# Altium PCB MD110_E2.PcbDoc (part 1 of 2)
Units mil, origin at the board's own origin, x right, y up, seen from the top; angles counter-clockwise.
Board outline 2320.49 x 1909 mil, 4 copper layers (Top Layer, Signal Layer 1, Signal Layer 2, Bottom Layer), stack 61.2 mil thick; 89 components, 32 nets, 187 pads, 40 vias.
Unrouted connection lines stored in the file: 7.
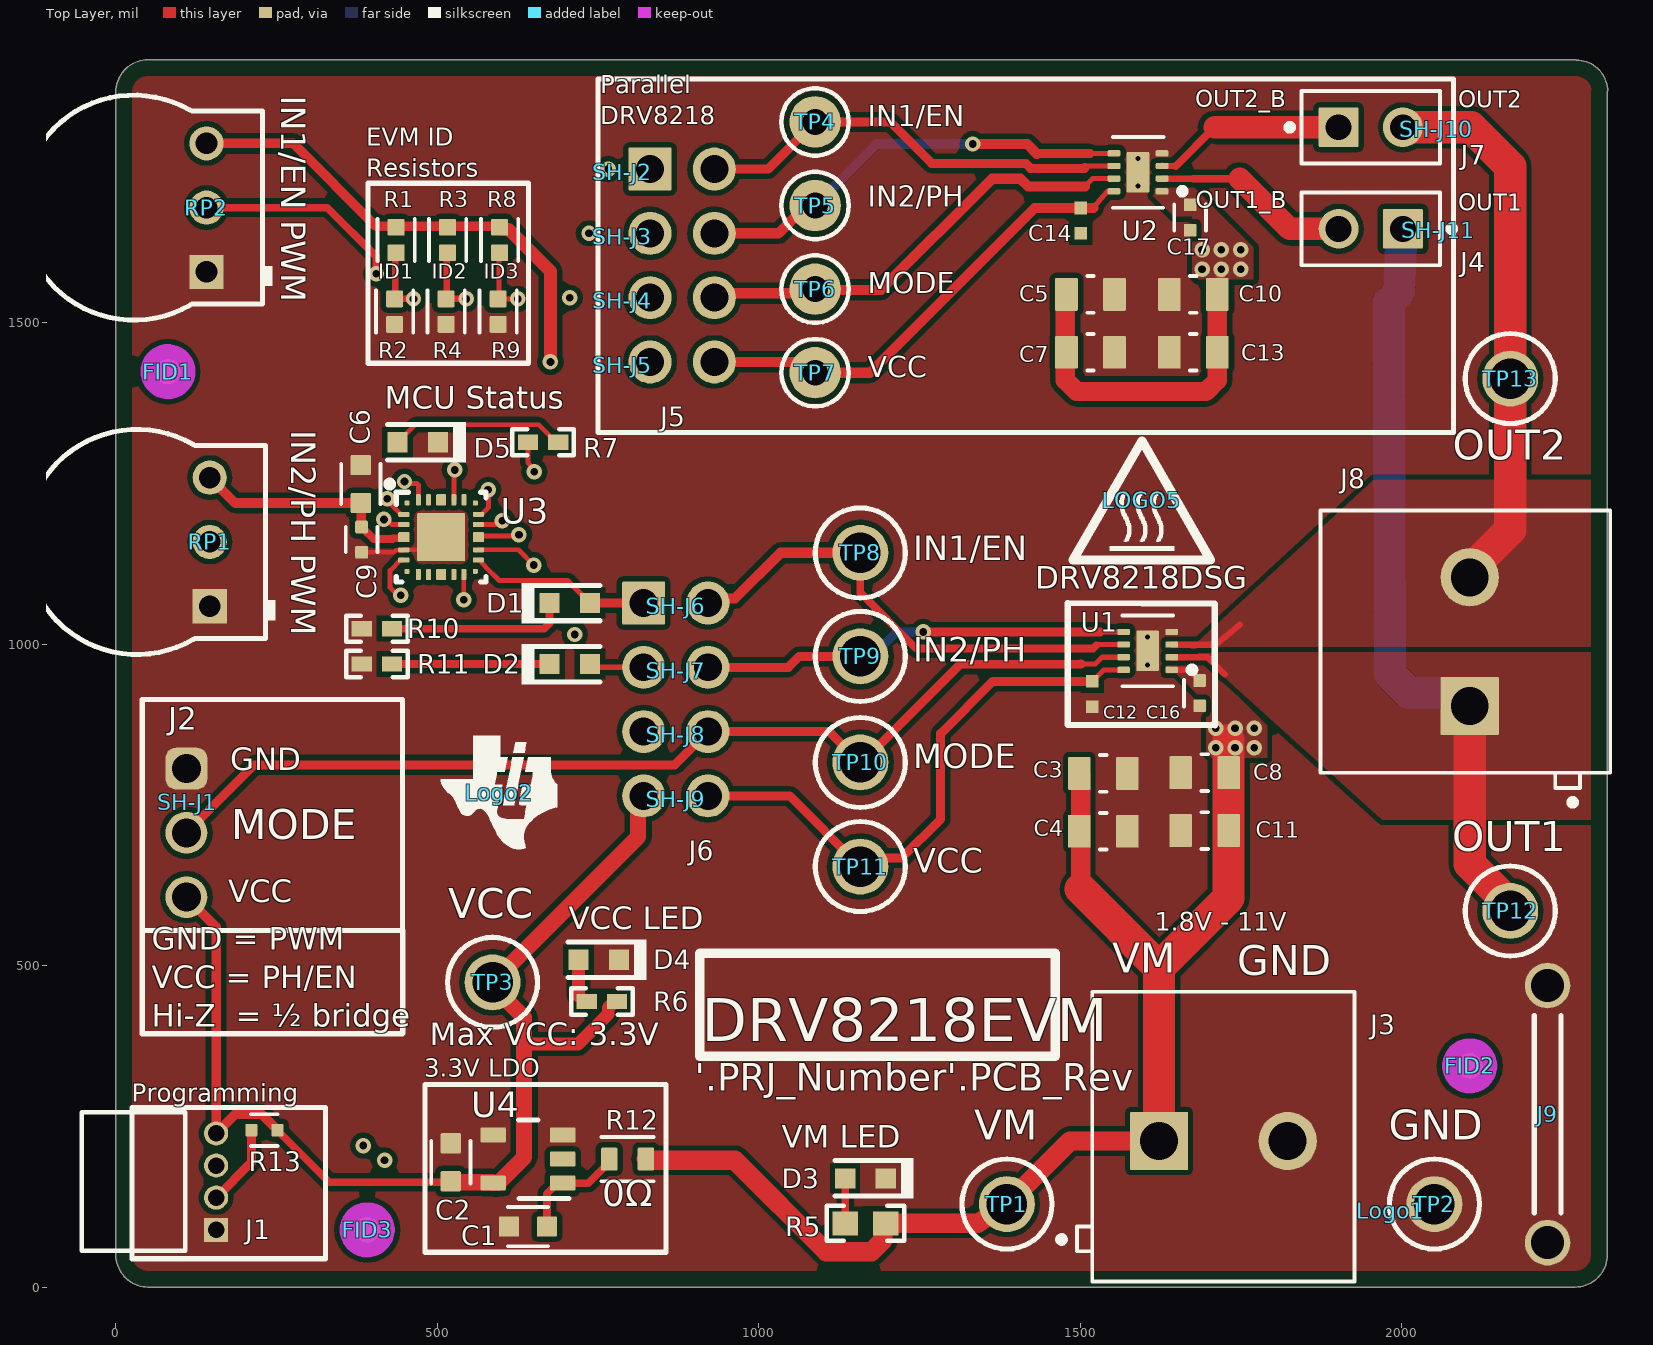
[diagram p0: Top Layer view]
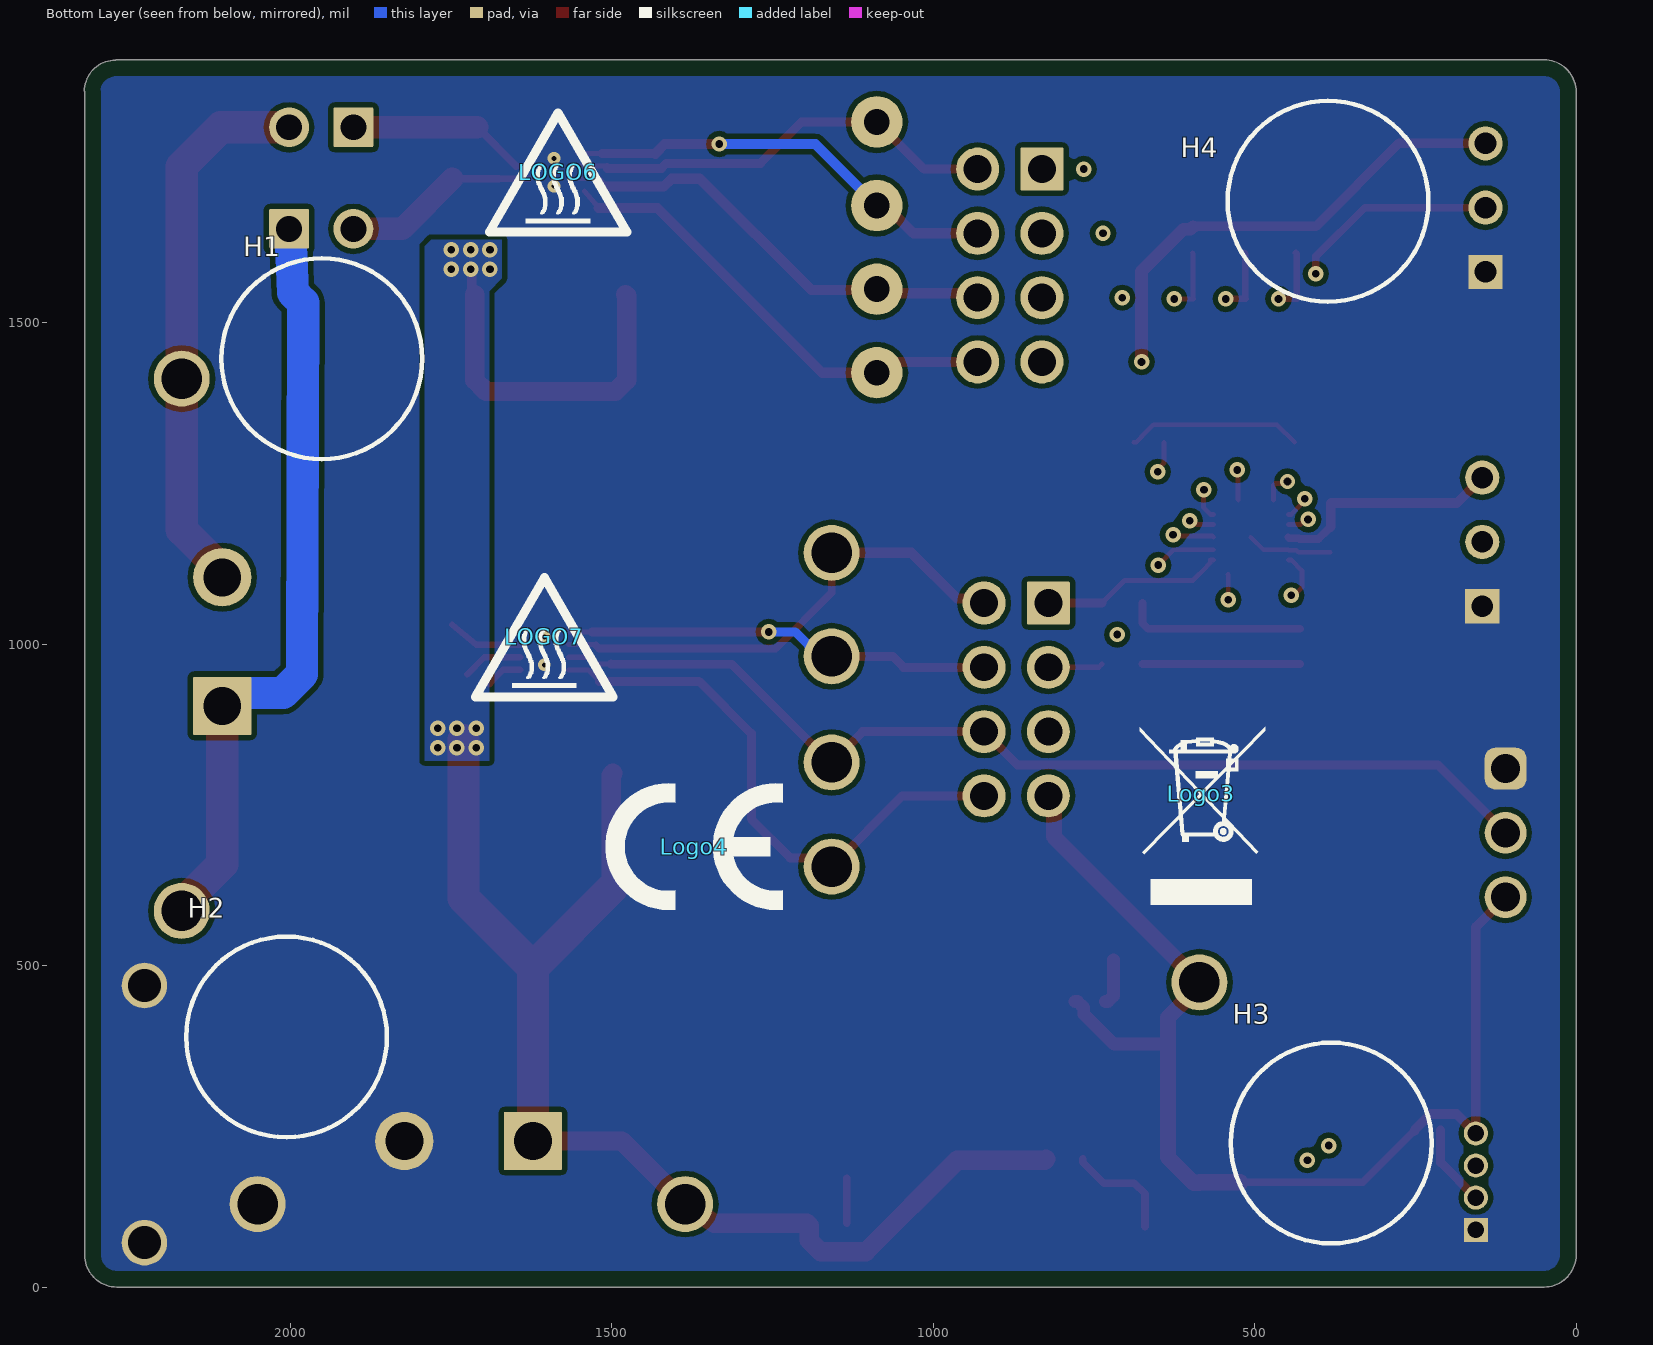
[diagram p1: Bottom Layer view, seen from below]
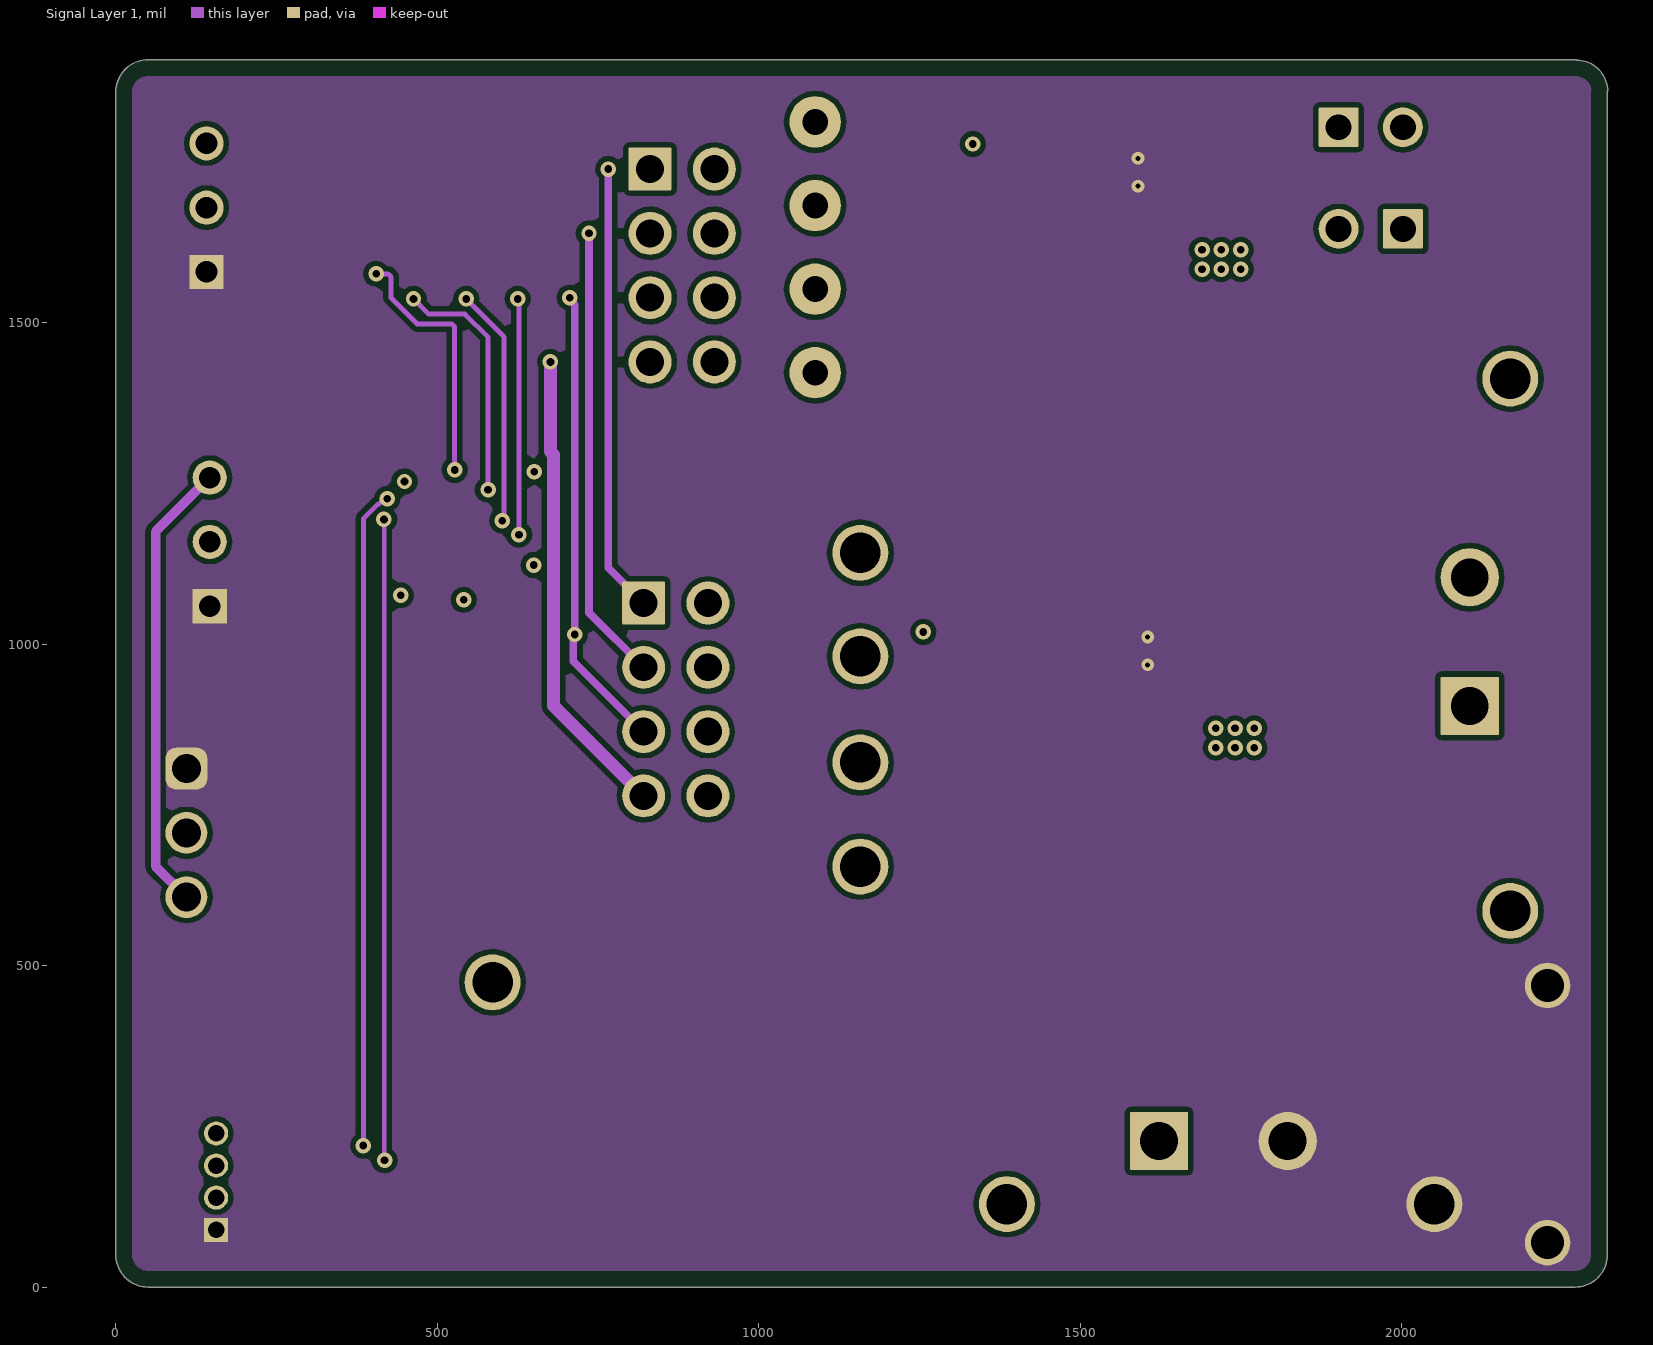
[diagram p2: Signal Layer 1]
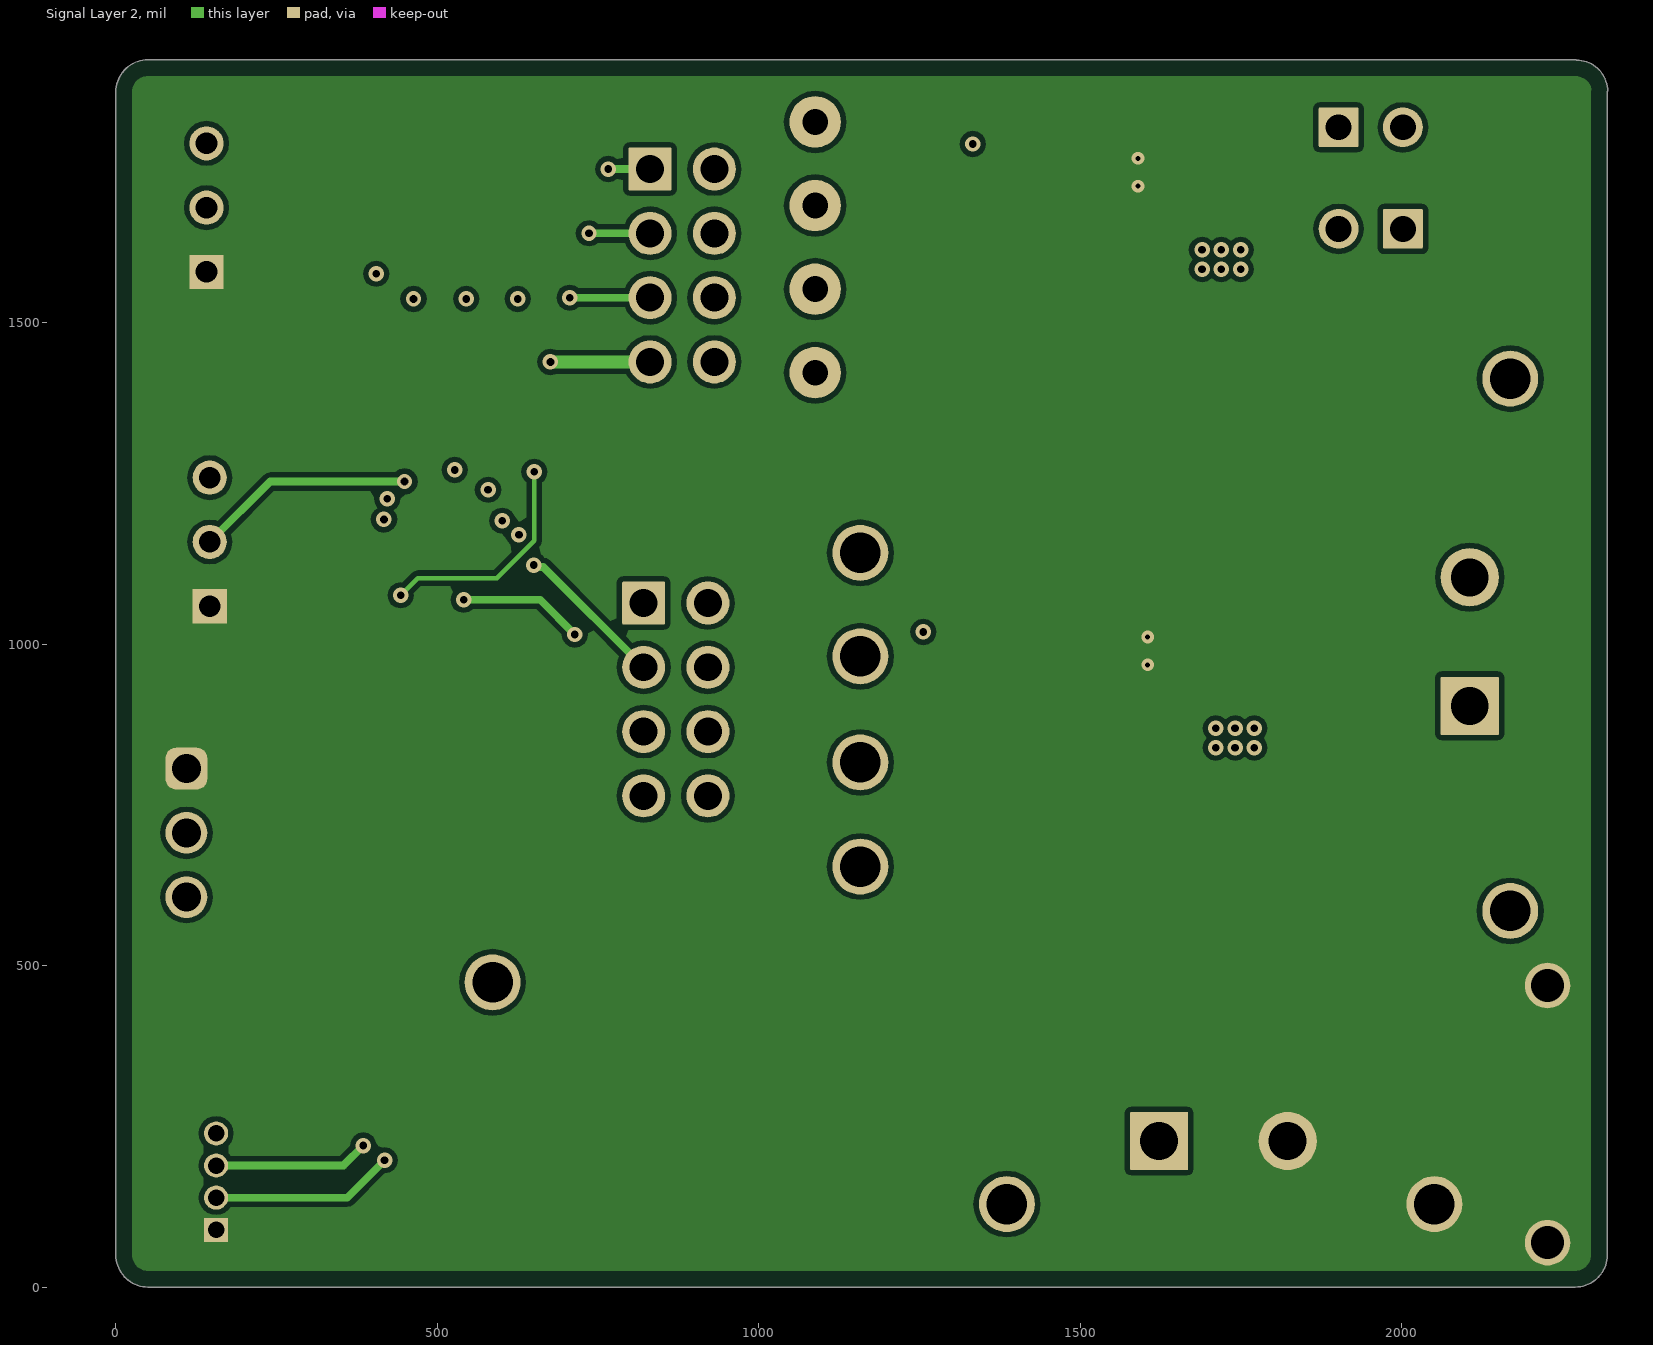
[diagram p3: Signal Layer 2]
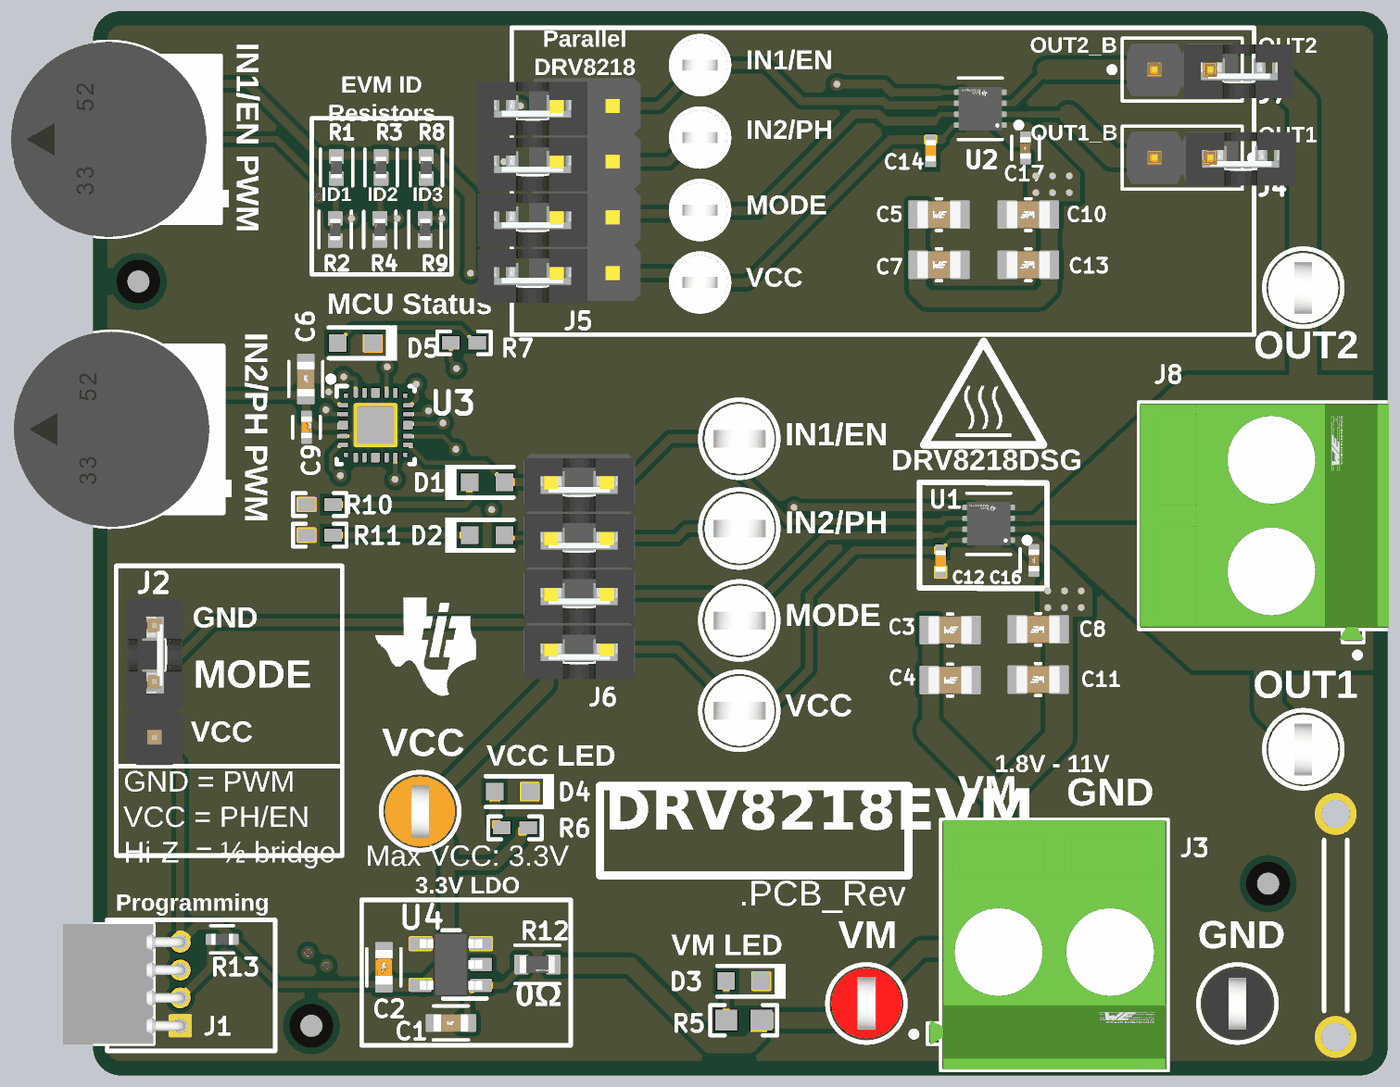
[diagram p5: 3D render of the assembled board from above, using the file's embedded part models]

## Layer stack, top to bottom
Top Solder: solder mask 0.4, Solder Resist, Dk 3.5
Top Layer: signal copper 2.8
Dielectric 1: prepreg 11.4, FR4 370, Dk 4.2
Signal Layer 1: signal copper 1.4
Dielectric 2: core 30, FR4 370, Dk 4.2
Signal Layer 2: signal copper 1.4
Dielectric 3: prepreg 11.4, FR4 370, Dk 4.2
Bottom Layer: signal copper 2.8
Bottom Solder: solder mask 0.4, Solder Resist, Dk 3.5

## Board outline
50,0 cw(c50,50) 0,50 0,1859 cw(c50,1859) 50,1909 2272,1909 2272,1908.49 cw(c2272,1860) 2320.49,1860 2320,1860 2320,50 cw(c2270,50) 2270,0

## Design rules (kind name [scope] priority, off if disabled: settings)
AcuteAngle [All] p1: minimum=4.50000000000000E+0001 checktracksonly=FALSE
AssemblyTestPointUsage [All] p1: valid=2
BoardOutlineClearance BoardOutlineClearance_MountingHoles [OnCopper and InComponentClass('Mounting Holes')] p1: gap=25 ignorepadtopadclearanceinfootprint=FALSE
BoardOutlineClearance BoardOutlineClearance_Poly [OnCopper and IsPoly] p2: gap=25 ignorepadtopadclearanceinfootprint=FALSE
BoardOutlineClearance [OnCopper and Not InComponentClass('Logo') and not InComponentClass('FiducialMark') and not InRegion(1000,500,4000,800) and not InPoly] p3: gap=10 ignorepadtopadclearanceinfootprint=FALSE
Clearance Clearance_OUTx [InNet('OUT1')] p1: gap=8 ignorepadtopadclearanceinfootprint=TRUE
Clearance Clearance_Keepouts [((IsTrack Or IsArc) And Not InPoly) And IsFree and IsKeepOut vs ((IsTrack Or IsArc) And Not InPoly) And IsFree and IsKeepOut] p2: gap=0 ignorepadtopadclearanceinfootprint=FALSE
Clearance Clearance_FiducialMark [IsKeepOut and InComponentClass('FiducialMark') vs IsPad and InComponentClass('FiducialMark')] p3: gap=0 ignorepadtopadclearanceinfootprint=FALSE
Clearance Clearance_Poly [InPolygon] p4: gap=8 ignorepadtopadclearanceinfootprint=TRUE
Clearance [All] p5: gap=7.87 ignorepadtopadclearanceinfootprint=TRUE
ComponentClearance ComponentClearance_Shunt2Header [InComponentClass('Header') vs InComponentClass('Shunt')] p1: gap=0 collisioncheckmode=3 verticalgap=0 showdistances=FALSE
ComponentClearance ComponentClearance_Shunt2Shunt [InComponentClass('Shunt') vs InComponentClass('Shunt')] p2: gap=0 collisioncheckmode=3 verticalgap=0 showdistances=FALSE
ComponentClearance ComponentClearance_MountingHoles_FiducialMarks [InComponentClass('Mounting Holes') vs InComponentClass('FiducialMark')] p3: gap=50 collisioncheckmode=3 verticalgap=10 showdistances=FALSE
ComponentClearance ComponentClearance_Logo [InComponentClass('Logo')] p4: gap=50 collisioncheckmode=3 verticalgap=10 showdistances=FALSE
ComponentClearance ComponentClearance_ScrewToNut [(HasFootprint('NY PMS 440 0025 PH')) vs (HasFootprint('Keystone_1902C'))] p5: gap=5 collisioncheckmode=3 verticalgap=10 showdistances=FALSE
ComponentClearance ComponentClearance_MountingHoles [InComponentClass('Mounting Holes')] p6: gap=250 collisioncheckmode=3 verticalgap=100000 showdistances=FALSE
ComponentClearance ComponentClearance_SmallPassives [HasFootprint('0201*') or HasFootprint('0402*') or HasFootprint('0508') or HasFootprint('0603*') or HasFootprint('0612') or HasFootprint('0805*') or HasFootprint('0815*') or HasFootprint('0830*') or HasFootprint('1206*') or HasFootprint('1210*') or HasFootprint('1808*') or HasFootprint('1812*') or HasFootprint('1825*') or HasFootprint('2010*') or HasFootprint('2220*') or HasFootprint('2225*') or HasFootprint('2512*') or HasFootprint('2728*') or HasFootprint('3518*') vs HasFootprint('0201*') or HasFootprint('0402*') or HasFootprint('0508') or HasFootprint('0603*') or HasFootprint('0612') or HasFootprint('0805*') or HasFootprint('0815*') or HasFootprint('0830*') or HasFootprint('1206*') or HasFootprint('1210*') or HasFootprint('1808*') or HasFootprint('1812*') or HasFootprint('1825*') or HasFootprint('2010*') or HasFootprint('2220*') or HasFootprint('2225*') or HasFootprint('2512*') or HasFootprint('2728*') or HasFootprint('3518*')] p7: gap=14.96 collisioncheckmode=3 verticalgap=10 showdistances=FALSE
ComponentClearance ComponentClearance_THtoSMT [IsThruComponent vs IsSMTComponent] p8: gap=30 collisioncheckmode=3 verticalgap=30 showdistances=FALSE
ComponentClearance ComponentClearance_THtoTH [IsThruComponent vs IsThruComponent] p9: gap=30 collisioncheckmode=3 verticalgap=30 showdistances=FALSE
ComponentClearance [All] p10: gap=30 collisioncheckmode=3 verticalgap=10 showdistances=FALSE
DiffPairsRouting [All] p1: maxlimit=100 minlimit=10 mostfreqgap=10 toplayer_minwidth=6.3 toplayer_maxwidth=15 toplayer_prefwidth=10 midlayer1_minwidth=15 midlayer1_maxwidth=15 midlayer1_prefwidth=15 midlayer2_minwidth=15 midlayer2_maxwidth=15 midlayer2_prefwidth=15 bottomlayer_minwidth=6.3 bottomlayer_maxwidth=15 bottomlayer_prefwidth=10 maxuncoupledlength=1000
FabricationTestPointUsage TestPointUsage [All] p1: valid=2 allowmultiple=FALSE
FabricationTestpoint Testpoint [All] p1: side=3 testpointundercomponent=TRUE minsize=40 maxsize=100 preferedsize=60 minholesize=0 maxholesize=40 preferedholesize=32 testpointgrid=1 allowsidetop=TRUE allowsidebottom=TRUE usegrid=TRUE gridtolerance=0.01
FanoutControl Fanout_LCC [IsLCC] p1: bgadir=Out bgaviamode=Centered fanoutstyle=Auto fanoutdirection=Alternating viagrid=1 // Fanout_LCC (Default Rule)
FanoutControl Fanout_BGA [IsBGA] p2: bgadir=Out bgaviamode=Centered fanoutstyle=Auto fanoutdirection=Alternating viagrid=1 // Fanout_BGA (Default Rule)
FanoutControl Fanout_Default [All] p4: bgadir=Out bgaviamode=Centered fanoutstyle=Auto fanoutdirection=Alternating viagrid=1 // Fanout_Default (Default Rule)
FanoutControl Fanout_Small [(CompPinCount < 5)] p5: bgadir=Out bgaviamode=Centered fanoutstyle=Auto fanoutdirection=OutThenIn viagrid=1 // Fanout_Small (Default Rule)
HoleSize [All] p1: absolutevalues=TRUE maxlimit=251 minlimit=7.87 maxpercent=80.000 minpercent=20.000
MinimumAnnularRing MinimumAnnularRing_ThermalPadVias [IsVia and InAnyComponent] p1: minimumring=5.91
MinimumAnnularRing [All] p2: minimumring=7.87
MinimumSolderMaskSliver MinimumSolderMaskSliver_Logo [InComponentClass('Logo') vs InComponentClass('Logo')] p1: minsoldermaskwidth=0.7
MinimumSolderMaskSliver [All] p2: minsoldermaskwidth=3.94
PlaneClearance [All] p1: clearance=12
PlaneConnect [All] p1: planeconnectstyle=Direct reliefexpansion=10 reliefentries=4 reliefconductorwidth=10 reliefairgap=10
PolygonConnect PolygonConnect_1 [InNetClass('Power-Net') vs IsNamedPolygon('TOP_LAYER_EZFET_USB_SHIELD_P201')] p1: connectstyle=Direct reliefconductorwidth=10 reliefentries=4 polygonreliefangle="90 Angle" airgapwidth=10
PolygonConnect [All] p2: connectstyle=Direct reliefconductorwidth=10 reliefentries=4 polygonreliefangle="90 Angle" airgapwidth=10
RoutingVias ThermalPadVias [IsVia and InAnyComponent] p1: holewidth=7.87 width=19.68 viastyle="Through Hole" minholewidth=7.87 minwidth=19.68 maxholewidth=12.99 maxwidth=23.62
RoutingVias [All] p2: holewidth=16 width=34 viastyle="Through Hole" minholewidth=7.87 minwidth=26 maxholewidth=40 maxwidth=65
SilkToBoardRegionClearance [Not ((IsComment or IsDesignator) And (Hide <> 'False')) and not InRegion(1000,500,4000,800)] p1:
SilkToSilkClearance SilkToSilkClearance_Pb-FreeLogo [(HasFootprint('Pb-Free_Overlay_Medium') OR HasFootprint('Pb-Free_Overlay_Small')) vs (HasFootprint('Pb-Free_Overlay_Medium') OR HasFootprint('Pb-Free_Overlay_Small'))] p1: silktosilkclearance=0
SilkToSilkClearance [All] p2: silktosilkclearance=3.94
SilkToSolderMaskClearance SilkToComponentPadClearance [(IsPad or IsFill or IsRegion) and InAnycomponent] p1: minsilkscreentomaskgap=5 clearancetoexposedcopper=TRUE
SilkToSolderMaskClearance "Silk to Solder Mask Opening" [All] p2: minsilkscreentomaskgap=3.94 clearancetoexposedcopper=FALSE
SolderMaskExpansion [All] p1: expansion=1.97 istentingtop=FALSE
UnRoutedNet [All] p1: checkbadconnections=TRUE
Width [All] p1: maxlimit=65 minlimit=4 preferedwidth=15 minimp=50.000000 maximp=50.000000 favimp=50.000000 checkconnectedcopper=TRUE
13 further rules are at their usual default settings.

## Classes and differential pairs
component class Shunt: SH-J1 SH-J2 SH-J3 SH-J4 SH-J5 SH-J6 SH-J7 SH-J8 SH-J9 SH-J10 SH-J11
component class MD110_E2_Schematic: C1 C2 C3 C4 C5 C6 C7 C8 C9 C10 C11 C12 C13 C14 C16 C17 D1 D2 D3 D4 D5 J1 J2 J3 J4 J5 J6 J7 J8 J9 R1 R2 R3 R4 R5 R6 R7 R8 R9 R10 R11 R12 R13 RP1 RP2 SH-J1 SH-J2 SH-J3 SH-J4 SH-J5 SH-J6 SH-J7 SH-J8 SH-J9 SH-J10 SH-J11 TP1 TP2 TP3 TP4 TP5 TP6 TP7 TP8 TP9 TP10 TP11 TP12 TP13 U1 U2 U3 U4
component class FiducialMark: FID1 FID2 FID3
component class MD110_E2_Hardware: !PCB1 FID1 FID2 FID3 H1 H2 H3 H4 Logo1 Logo2 Logo3 Logo4 LOGO5 LOGO6 LOGO7 ZZ1 ZZ5
component class Header: J2 J4 J5 J6 J7
component class Logo: Logo2
component class AssemblyNote: ZZ1 ZZ5

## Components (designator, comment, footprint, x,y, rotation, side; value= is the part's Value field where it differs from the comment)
C1 "885012206126" FP-885012206126_0603-MFG 641,94 r0 top value=1µF
C2 "885012106012" FP-885012106012_0603-MFG 521,194 r270 top value=4.7µF
C3 "885012107019" FP-885012107019_0805-MFG 1536,799 r0 top value=22µF
C4 "885012107019" FP-885012107019_0805-MFG 1536,709 r0 top value=22µF
C5 "885012107019" FP-885012107019_0805-MFG 1516,1544 r0 top value=22µF
C6 "885012206126" FP-885012206126_0603-MFG 381,1249 r270 top value=1µF
C7 "885012107019" FP-885012107019_0805-MFG 1516,1454 r0 top value=22µF
C8 "885012107019" FP-885012107019_0805-MFG 1693.72,800.06 r180 top value=22µF
C9 "885012205018" FP-885012205018_0402-MFG 382.22,1162.53 r90 top value=100nF
C10 "885012107019" FP-885012107019_0805-MFG 1676,1544 r180 top value=22µF
C11 "885012107019" FP-885012107019_0805-MFG 1693.72,710.06 r180 top value=22µF
C12 "885012205018" WCAP-CSGP_0402_L1W0.5H0.5 1519,922.5 r90 top
C13 "885012107019" FP-885012107019_0805-MFG 1676,1454 r180 top value=22µF
C14 "885012205018" WCAP-CSGP_0402_L1W0.5H0.5 1501,1658.76 r90 top
C16 "885012205085" FP-885012205085_0402-MFG 1686,923.68 r90 top value=100nF
C17 "885012205085" FP-885012205085_0402-MFG 1671,1663.68 r90 top value=100nF
D1 "150060BS75000" WL-SMCW_Blue 706,1064 r0 top value=Blue
D2 "150060BS75000" WL-SMCW_Blue 706,969 r0 top value=Blue
D3 "150060VS75000" WL-SMCW_GREEN 1166,169 r180 top value=Green
D4 "150060VS75000" WL-SMCW_GREEN 751,509 r180 top value=Green
D5 "150060VS75000" WL-SMCW_GREEN 469.5,1314 r180 top value=Green
FID1 "Fiducial" Fiducial10-20 81,1424 r90 top
FID2 "Fiducial" Fiducial10-20 2106,344 r90 top
FID3 "Fiducial" Fiducial10-20 391,89 r90 top
H1 "SJ61A1" Bumpon_SJ61A1 1951,1444 r180 bottom
H2 "SJ61A1" Bumpon_SJ61A1 2006,389 r180 bottom
H3 "SJ61A1" Bumpon_SJ61A1 381,224 r180 bottom
H4 "SJ61A1" Bumpon_SJ61A1 386,1689 r180 bottom
J1 "851-43-004-20-001000" CONN_851-43-004-20-001000 156,164 r270 top
J2 "61300311121" WURTH_61300311121 109.76,706.48 r270 top
J3 "691236510002" FP-691236510002_HHR2-MFG 1711,234 r0 top
J4 "PH1-02-UA" FP-PH1-02-UA_HDR2-MFG 1952,1646 r180 top
J5 "61300821121" FP-61300821121_HDR8-MFG 881,1589 r270 top
J6 "61300821121" FP-61300821121_HDR8-MFG 871,914 r270 top
J7 "PH1-02-UA" FP-PH1-02-UA_HDR2-MFG 1952,1804 r0 top
J8 "691236510002" FP-691236510002_HHR2-MFG 2099.11,992.19 r90 top
J9 "D3082-05" Harwin_D3082-05 2227,269 r270 top
Logo1 "FCC disclaimer" FCC_disclaimer 1983,119 r180 top
Logo2 "Texas Instruments" TI_Symbol_Overlay_Small 596,769 r0 top
Logo3 "WEEE logo" WEEE_Minimum 583,767 r180 bottom
Logo4 "CE Mark" CE_Mark_5mm 1372,685 r180 bottom
LOGO5 "CAUTION HOT SURFACE" IEC_HotSurface_Small 1596,1224 r0 top
LOGO6 "CAUTION HOT SURFACE" IEC_HotSurface_Small 1583.6,1733.84 r180 bottom
LOGO7 "CAUTION HOT SURFACE" IEC_HotSurface_Small 1605,1011.15 r180 bottom
R1 "CR0402-10W-000T" FP-CR0402-10W-000T_0402-IPC_A 435.94,1628.58 r90 top value=0Ω
R2 "CR0402-10W-000T" FP-CR0402-10W-000T_0402-IPC_A 433.71,1517.27 r90 top value=0Ω
R3 "CR0402-10W-000T" FP-CR0402-10W-000T_0402-IPC_A 515.94,1628.58 r90 top value=0Ω
R4 "CR0402-10W-000T" FP-CR0402-10W-000T_0402-IPC_A 513.71,1517.27 r90 top value=0Ω
R5 "ESR03EZPJ102" 0603 1166,99 r180 top value=1.0k
R6 "CRCW0402330RFKED" 0402 756,444 r180 top value=330
R7 "CRCW0402330RFKED" 0402 664.62,1314 r0 top value=330
R8 "CR0402-10W-000T" FP-CR0402-10W-000T_0402-IPC_A 596.95,1628.58 r90 top value=0Ω
R9 "CR0402-10W-000T" FP-CR0402-10W-000T_0402-IPC_A 594.73,1517.27 r90 top value=0Ω
R10 "CRCW0402330RFKED" 0402 406,1024 r180 top value=330
R11 "CRCW0402330RFKED" 0402 406,969 r180 top value=330
R12 "ERJ-3GEY0R00V" FP-ERJ-3GEY0R00V_0603-MFG 796,199 r180 top value=0Ω
R13 "ERJ-2GEJ473X" FP-ERJ-2GEJ473X_0402-MFG 231,244 r180 top value=47k
RP1 "3352T-1-503LF" Bourns_3352T 146,1159 r90 top value=50k
RP2 "3352T-1-503LF" Bourns_3352T 141,1679 r90 top value=50k
SH-J1 "60900213421" Wurth_60900213421 111,754 r270 top
SH-J2 "60900213421" Wurth_60900213421 787.54,1734 r180 top
SH-J3 "60900213421" Wurth_60900213421 787.54,1634 r180 top
SH-J4 "60900213421" Wurth_60900213421 787.54,1534 r180 top
SH-J5 "60900213421" Wurth_60900213421 787.54,1434 r180 top
SH-J6 "60900213421" Wurth_60900213421 871,1059 r180 top
SH-J7 "60900213421" Wurth_60900213421 871,959 r180 top
SH-J8 "60900213421" Wurth_60900213421 871,859 r180 top
SH-J9 "60900213421" Wurth_60900213421 871,759 r180 top
SH-J10 "60900213421" Wurth_60900213421 2054,1801 r180 top
SH-J11 "60900213421" Wurth_60900213421 2057,1644 r180 top
TP1 "5010" Keystone5010 1386,129 r180 top
TP2 "5011" Keystone5011 2051,129 r0 top
TP3 "5013" Keystone5013 586,474 r0 top
TP4 "5002" Keystone5002 1087.72,1812.28 r90 top
TP5 "5002" Keystone5002 1087.72,1682.28 r90 top
TP6 "5002" Keystone5002 1087.72,1552.28 r90 top
TP7 "5002" Keystone5002 1087.72,1422.28 r90 top
TP8 "5012" Keystone5012 1158,1142 r90 top
TP9 "5012" Keystone5012 1158,981 r90 top
TP10 "5012" Keystone5012 1158,816 r90 top
TP11 "5012" Keystone5012 1158,654 r90 top
TP12 "5012" Keystone5012 2169,585 r0 top
TP13 "5012" Keystone5012 2169,1413 r0 top
U1 "DRV8218DSGR" DSG0008A-MFG 1605,989.5 r180 top
U2 "DRV8218DSGR" DSG0008A-MFG 1590,1734 r180 top
U3 "MSP430FR2100IRLLR" RLL0024A 506,1166.4 r0 top
U4 "TPS7B6933DBVR" DBV0005A_N 641,199 r180 top
ZZ1 "These assemblies are ESD sensitive, ESD precautions shall be observed." AssemblyNote 422,-319 r0 top
ZZ5 "This Assembly Note is for PCB labels only" AssemblyNoteLabel 491,-219 r0 top

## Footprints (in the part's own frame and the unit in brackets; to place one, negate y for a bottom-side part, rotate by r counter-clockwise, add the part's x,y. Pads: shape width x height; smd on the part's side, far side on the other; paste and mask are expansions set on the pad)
0402 [mm] "0402 from SM-752 data"
  rect 0.8x0.6 smd: 1(-0.6,0) 2(0.6,0)
  silkscreen extent -1.22,-0.52 1.22,0.52, body extent -0.55,-0.3 0.55,0.3, height 0.6
0603 [mm] "0603 from SM-752 data"
  rect 1x0.95 smd: 1(-0.8,0) 2(0.8,0)
  silkscreen extent -1.52,-0.69 1.52,0.69, body extent -0.87,-0.47 0.87,0.47, height 1
AssemblyNote [mil] "Assembly Note"
AssemblyNoteLabel [mil] "Assembly Note for PCB Labels"
Bourns_3352T [mm] "TH, 3-Leads, Body 9.53x8.89mm, Pitch 2.54mm"
  rect 1.35x1.35 hole 0.85: 1(-2.54,0)
  round 1.35 hole 0.85: 2(0,0) 3(2.54,0)
  silkscreen extent -4.44,-2.6 4.44,7.31, body extent -4.44,-2.21 4.45,7.32, height 3.81
Bumpon_SJ61A1 [mil] "3M Cylindrical Bumpon black"
  round 1 on Mech4: 0(0,0)
  silkscreen extent -156,-156 156,156, body extent -156,-156 156,156, height 201
CE_Mark_5mm [mil] "Minimum text height for CE Mark"
  silkscreen extent -138,-98 138,98
CONN_851-43-004-20-001000 [mm] "MILL-MAX"
  rect 0.95x0.95 hole 0.65: 1(1.905,0)
  round 0.95 hole 0.65: 2(0.635,0) 3(-0.635,0) 4(-1.905,0)
  silkscreen extent -2.73,-5.31 2.73,-1.22, body extent -2.73,-5.31 2.73,0.23, height 2.23
DBV0005A_N [mm] "SOT23, 5-Leads, Body 2.9x1.6mm, Pitch 0.95mm, Lead Span 2.8mm, IPC Medium Density"
  rrect17% 1x0.6 smd: 1(-1.375,0.95) 2(-1.375,0) 3(-1.375,-0.95) 4(1.375,-0.95) 5(1.375,0.95)
  silkscreen extent -1.63,-1.55 0.38,1.55, body extent -1.42,-1.46 1.42,1.46, height 1.09
DSG0008A-MFG [mm] "Recommended Land Pattern"
  rrect40% 0.5x0.25 smd paste+0 mask+0: 1(-0.95,0.75) 2(-0.95,0.25) 3(-0.95,-0.25) 4(-0.95,-0.75) 5(0.95,-0.75) 6(0.95,-0.25) 7(0.95,0.25) 8(0.95,0.75)
  rrect11% 0.9x1.6 smd paste-1000 mask+0: 9(0,0)
  silkscreen extent -1.88,-1.39 1,1.4, body extent -1,-1 1,1, height 0.8
FCC_disclaimer [mil]
Fiducial10-20 [mm]
  round 1 smd mask+0.5: 1(0,0)
  Top Layer keep-out circle w1.178: c0,0 r0.5
FP-61300821121_HDR8-MFG [mm]
  rrect6% 1.7x1.7 hole 1.1 paste-2539.97 mask+0: 1(-3.81,-1.27)
  round 1.7 hole 1.1 paste-2539.97 mask+0: 2(-3.81,1.27) 3(-1.27,-1.27) 4(-1.27,1.27) 5(1.27,-1.27) 6(1.27,1.27) 7(3.81,-1.27) 8(3.81,1.27)
  body extent -5.33,-2.72 5.33,2.72, height 0.25
FP-691236510002_HHR2-MFG [mm]
  rrect4% 2.3x2.3 hole 1.5 paste-2539.97 mask+0: 1(-2.24,-0.175)
  round 2.3 hole 1.5 paste-2539.97 mask+0: 2(2.84,-0.175)
  silkscreen extent -6.22,-5.72 5.48,5.72, body extent -5.58,-5.82 5.58,5.82, height 0.25
FP-885012106012_0603-MFG [mm]
  rrect13% 0.8x0.8 smd paste+0 mask+0: 1(-0.75,0) 2(0.75,0)
  silkscreen extent -0.85,-0.77 0.85,0.77, body extent -1.25,-0.55 1.25,0.55, height 0.25
FP-885012107019_0805-MFG [mm] "Recommended Land Pattern"
  rrect11% 0.9x1.3 smd paste+0 mask+0: 1(-0.95,0) 2(0.95,0)
  silkscreen extent -0.13,-0.72 0.13,0.72, body extent -1.5,-0.82 1.5,0.82, height 0.25
FP-885012205018_0402-MFG [mm]
  rrect20% 0.5x0.5 smd paste+0 mask+0: 1(-0.5,0) 2(0.5,0)
  silkscreen extent -0.5,-0.63 0.5,0.63, body extent -0.85,-0.38 0.85,0.38, height 0.25
FP-885012205085_0402-MFG [mm]
  rrect20% 0.5x0.5 smd paste+0 mask+0: 1(-0.5,0) 2(0.5,0)
  silkscreen extent -0.53,-0.63 0.53,0.63, body extent -0.85,-0.38 0.85,0.38, height 0.25
FP-885012206126_0603-MFG [mm]
  rrect13% 0.8x0.8 smd paste+0 mask+0: 1(-0.75,0) 2(0.75,0)
  silkscreen extent -0.8,-0.77 0.8,0.77, body extent -1.25,-0.58 1.25,0.58, height 0.25
FP-CR0402-10W-000T_0402-IPC_A [mil]
  rrect15% 26.19x26.48 smd paste+0 mask+0: 1(-19.83,0) 2(19.83,0)
  silkscreen extent -33,-29 33,29, body extent -41,-21 41,21, height 10
FP-ERJ-2GEJ473X_0402-MFG [mm]
  rrect21% 0.475x0.5 smd paste+0 mask+0: 1(-0.513,0) 2(0.513,0)
  silkscreen extent -0.53,-0.63 0.53,0.63, body extent -0.85,-0.38 0.85,0.38, height 0.25
FP-ERJ-3GEY0R00V_0603-MFG [mm]
  rrect15% 0.65x0.9 smd paste+0 mask+0: 1(-0.725,0) 2(0.725,0)
  silkscreen extent -1.03,-0.87 1.03,0.87, body extent -1.15,-0.58 1.15,0.58, height 0.25
FP-PH1-02-UA_HDR2-MFG [mm]
  rrect6% 1.57x1.57 hole 1.02 paste-1000 mask+0: 1(-1.27,0)
  round 1.57 hole 1.02 paste-1000 mask+0: 2(1.27,0)
  silkscreen extent -3.33,-1.44 2.73,1.44, body extent -2.83,-1.54 2.83,1.54, height 0.25
Harwin_D3082-05 [mm] "Shorting Plug, 10.16mm spacing, TH"
  round 1.8 hole 1.3: 1(-5.08,0) 2(5.08,0)
  silkscreen extent -3.9,-0.53 3.9,0.53, body extent -5.6,-0.52 5.61,0.52, height 6.63
IEC_HotSurface_Small [mil]
  silkscreen extent -107,-93 107,92
Keystone5002 [mil] "For Keystone 500x miniature loop terminals"
  round 80 hole 40: 1(0,0)
  silkscreen extent -52,-52 52,52, body extent -49,-49 49,49, height 182
Keystone5010 [mil] "Keystone Multipurpose loops"
  round 87 hole 63: 1(0,0)
  silkscreen extent -70,-70 70,70, body extent -63,-63 63,62, height 319
Keystone5011 [mil] "Keystone Multipurpose loops"
  round 87 hole 63: 1(0,0)
  silkscreen extent -70,-70 70,70, body extent -63,-63 63,62, height 319
Keystone5012 [mil] "Keystone Multipurpose loops"
  round 87 hole 63: 1(0,0)
  silkscreen extent -70,-70 70,70, body extent -63,-63 63,62, height 319
Keystone5013 [mil] "Keystone Multipurpose loops"
  round 87 hole 63: 1(0,0)
  silkscreen extent -70,-70 70,70, body extent -63,-63 63,62, height 319
RLL0024A [mm] "QFN, 24-Leads, Body 3x3mm"
  rrect50% 0.45x0.2 smd: 1(-1.475,0.9) 2(-1.475,0.5) 4(-1.475,-0.5) 5(-1.475,-0.9) 13(1.475,-0.9) 14(1.475,-0.5) 16(1.475,0.5) 17(1.475,0.9)
  rrect25% 0.45x0.4 smd: 3(-1.475,0) 15(1.475,0)
  rrect50% 0.2x0.2 smd: 6(-1.35,-1.35) 12(1.35,-1.35) 18(1.35,1.35) 24(-1.35,1.35)
  rrect50% 0.2x0.45 smd: 7(-0.9,-1.475) 8(-0.5,-1.475) 10(0.5,-1.475) 11(0.9,-1.475) 19(0.9,1.475) 20(0.5,1.475) 22(-0.5,1.475) 23(-0.9,1.475)
  rrect25% 0.4x0.45 smd: 9(0,-1.475) 21(0,1.475)
  rrect5% 1.9x1.9 smd paste-1.9: 25(0,0)
  rrect6% 1.71x1.71 on Top Paste: ""(0,0)
  silkscreen extent -1.78,-1.78 1.78,1.78, body extent -1.58,-1.58 1.58,1.58, height 1.01
TI_Symbol_Overlay_Small [mil]
  silkscreen extent -90,-88 91,88
WCAP-CSGP_0402_L1W0.5H0.5 [mm] "Ceramic Capacitors, body 1x0.5mm"
  rect 0.5x0.5 smd: 1(-0.5,0) 2(0.5,0)
  body extent -0.5,-0.25 0.5,0.25, height 0.5
WEEE_Minimum [mil] "WEEElie bin"
  silkscreen extent -95,-172 99,104
WL-SMCW_Blue [mm] "SMD, 2-Leads, Body 1.6x0.8mm"
  rect 0.8x0.8 smd: 1(-0.8,0) 2(0.8,0)
  silkscreen extent -1.9,-0.8 1.2,0.8, body extent -0.85,-0.45 0.85,0.45, height 0.8
WL-SMCW_GREEN [mm] "WURTH"
  rect 0.8x0.8 smd: 1(-0.8,0) 2(0.8,0)
  silkscreen extent -1.9,-0.8 1.2,0.8, body extent -0.85,-0.45 0.85,0.45, height 0.8
Wurth_60900213421 [mil] "Shunt, 2.54mm, Black"
  round 1 on Mech3: 0(0,0)
  body extent -98,-48 98,48, height 338
WURTH_61300311121 [mm] "Header, 2.54mm, 3x1, TH"
  rrect50% 1.65x1.65 hole 1.15: 1(-2.54,0)
  round 1.65 hole 1.15: 2(0,0) 3(2.54,0)
  body extent -3.81,-1.27 3.81,1.27, height 8.54

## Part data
C1 C6: library part CMP-0120896-1, "1 µF ±10% 50V Ceramic Capacitor X7R 0603 (1608 Metric)", Digikey Part Number=732-885012206126CT-ND, Manufacturer="Wurth Electronics", Mouser Part Number=710-885012206126, Operating Temperature Range="-55°C to +125°C", TempCo=15%, Temperature Characteristic=X7R, Tolerance_%=10%, ValueDisplayed=1uF
C2: library part CMP-0097305-1, "4.7 µF ±20% 10V Ceramic Capacitor X5R 0603 (1608 Metric)", Digikey Part Number=732-7909-1-ND, Manufacturer="Wurth Electronics", Mouser Part Number=710-885012106012, Operating Temperature Range="-55°C to +85°C", TempCo=15%, Temperature Characteristic=X5R, Tolerance_%=20%, ValueDisplayed=4.7uF
C3 C4 C5 C7 C8 C10 C11 C13: library part CMP-0124987-1, "Ceramic Capacitor 0805 22µF ±20% 25V X5R", Manufacturer=Wurth, Operating Temperature Range="-55°C to +85°C", TempCo=15%, Temperature Characteristic=X5R, Tolerance_%=20%, ValueDisplayed=22uF
C9: library part CMP-0090362-1, "0.1µF ±10% 10V Ceramic Capacitor X7R 0402 (1005 Metric)", Digikey Part Number=732-7513-1-ND, Manufacturer="Wurth Electronics", Mouser Part Number=710-885012205018, Operating Temperature Range="-55°C to +125°C", TempCo=15%, Temperature Characteristic=X7R, Tolerance_%=10%, ValueDisplayed=100000pF
C12 C14: library part CMP-0119248-1, "0.1µF ±10% 10V Ceramic Capacitor X7R 0402 (1005 Metric)", Capacitance Tolerance=+/-10%, Case/Size Code=0402, Insulation Resistance=5GOhm, Manufacturer="Wurth Elektronik", Operating Temperature Max=125°C, Operating Temperature Min=-55°C, Rated Voltage (DC)=10V
C16 C17: library part CMP-0090365-1, "CAP, CERAMIC, 0402, X7R, 100nF, 25V, ±15 %, SMD", Manufacturer="Wurth Electronics", Operating Temperature Range="-55°C to +125°C", TempCo=15%, Temperature Characteristic=X7R, Tolerance_%=10%, ValueDisplayed=100nF
D1 D2: library part CMP-0002946-3, "LED, Blue, SMD", Color=Blue, Manufacturer="Wurth Elektronik", Power_TotalModule=105mW, Value1=0.105W, Value2=3.2V
D3 D4 D5: library part CMP-0002894-2, "LED, Green, SMD", Color=green, Manufacturer="Wurth Elektronik", Value1=W, Value2=2V
FID1 FID2 FID3: library part CMP-0077181-1, "Fiducial mark.  There is nothing to buy or mount.", Manufacturer=N/A
H1 H2 H3 H4: library part CMP-0003621-1, "Bumpon, Cylindrical, 0.312 X 0.200, Black", Manufacturer=3M, Supplier Part Number 1=SJ5746-0-ND
J1: library part CMP-0055060-1, "SOCKET .050\" GRID SIP 4 POS R/A, TH", Manufacturer=Mill-Max, Supplier Part Number 1=ED90474-ND
J2: library part CMP-0054796-4, "Header, 2.54 mm, 3x1, Gold, TH", Manufacturer="Wurth Elektronik", Supplier Part Number 1=732-5316-ND
J3 J8: library part CMP-0121282-1, "2 Position Wire to Board Terminal Block Horizontal with Board 0.200\" (5.08mm) Through Hole", Current_A=20A, Digikey Part Number=732-10995-ND, Manufacturer="Wurth Electronics", Mouser Part Number=710-691236510002, Operating Temperature Range="-30°C to +120°C", Voltage_V=300V
J4 J7: library part CMP-0032636-1, "Connector Header Through Hole 2 position 0.100\" (2.54mm)", Current_A=3A, Digikey Part Number=2057-PH1-02-UA-ND, Manufacturer="Adam Tech", Operating Temperature Range=to, Voltage_V=250V
J5 J6: library part CMP-0087153-1, "CONN HEADER VERT 8POS 2.54MM", Current_A=3A, Manufacturer="Wurth Electronics", Voltage_V=250V
J9: library part CMP-0075110-1, "1mm Uninsulated Shorting Plug, 10.16mm spacing, TH", Manufacturer=Harwin, Supplier Part Number 1=952-1873-ND
Logo1: library part CMP-0074847-1, "FCC_disclaimer"
Logo2: library part CMP-0074838-1, "Texas Instrument Corporate Signature"
Logo3: library part CMP-0074769-4, Manufacturer="Texas Instruments"
Logo4: library part CMP-0074844-2, Manufacturer="Texas Instruments"
LOGO5 LOGO6 LOGO7: library part CMP-0074837-2, "IEC 61010-1 Hot Surface Warning", Manufacturer="Texas Instruments"
R1 R2 R3 R4 R8 R9: library part CMP-0094948-1, "0 Ohms Jumper 0.1W, 1/10W Chip Resistor 0402 (1005 Metric) - Thick Film", Digikey Part Number=2679-CR0402-10W-000TTR-ND, Manufacturer=Venkel, Operating Temperature Range="-55°C to +155°C", Power_W=100mW
R5: library part CMP-0084244-1, "RES, 1.0 k, 5%, 0.25 W, AEC-Q200 Grade 0, 0603", Manufacturer=Rohm, Power_W=250mW, TempCo="200 ppm/C", Tolerance_%=5%, Value2=0.25W, Value_Code=1k00, ValueDisplayed=1.0k
R6 R7 R10 R11: library part CMP-0078658-2, "RES, 330, 1%, 0.063 W, AEC-Q200 Grade 0, 0402", Manufacturer=Vishay-Dale, Power_W=63mW, Supplier Part Number 1=541-330LCT-ND, TempCo="100 ppm/C", Tolerance_%=1%, Value2=0.063W, Value_Code=330R, ValueDisplayed=330
R12: library part CMP-0089143-1, "0 Ohms Jumper 0.1W, 1/10W Chip Resistor 0603 (1608 Metric) Automotive AEC-Q200 Thick Film", Digikey Part Number=P0.0GCT-ND, Manufacturer=Panasonic, Mouser Part Number=667-ERJ-3GEY0R00V, Operating Temperature Range="-55°C to +155°C", Power_W=100mW, TempCo=-100/+600ppm/°C, Tolerance_%=5%
R13: library part CMP-0122885-1, "47 kOhms ±5% 0.1W, 1/10W Chip Resistor 0402 (1005 Metric) Automotive AEC-Q200 Thick Film", Digikey Part Number=P47KJCT-ND, Manufacturer=Panasonic, Mouser Part Number=667-ERJ-2GEJ473X, Operating Temperature Range="-55°C to +155°C", Power=100mW, TempCo=200ppm/°C, Tolerance_%=5%
RP1 RP2: library part CMP-0001777-2, "Trimming Potentiometer, 50K, 0.5W, TH", Manufacturer=Bourns, Supplier Part Number 1=3352T-503LF-ND
SH-J1 SH-J2 SH-J3 SH-J4 SH-J5 SH-J6 SH-J7 SH-J8 SH-J9 SH-J10 SH-J11: library part CMP-0003761-2, "Shunt, 2.54mm, Gold, Black", Manufacturer="Wurth Elektronik", Supplier Part Number 1=732-2678-ND
TP1: library part CMP-0055147-2, "Test Point, Multipurpose, Red, TH", Color=Red, Manufacturer="Keystone Electronics", Supplier Part Number 1=36-5010-ND
TP2: library part CMP-0055148-2, "Test Point, Multipurpose, Black, TH", Color=Black, Manufacturer="Keystone Electronics", Supplier Part Number 1=36-5011-ND
TP3: library part CMP-0055150-2, "Test Point, Multipurpose, Orange, TH", Color=Orange, Manufacturer="Keystone Electronics", Supplier Part Number 1=36-5013-ND
TP4 TP5 TP6 TP7: library part CMP-0055139-2, "Test Point, Miniature, White, TH", Color=White, Manufacturer="Keystone Electronics", Supplier Part Number 1=36-5002-ND
TP8 TP9 TP10 TP11 TP12 TP13: library part CMP-0055149-2, "Test Point, Multipurpose, White, TH", Color=White, Manufacturer="Keystone Electronics", Supplier Part Number 1=36-5012-ND
U1 U2: library part CMP-0126978-1, Manufacturer="Texas Instruments", Operating Temperature Range=to
U3: library part CMP-0080370-1, "16 MHz Ultra-Low-Power Microcontroller With 1 KB FRAM, 0.5 KB SRAM, 12 IO, 8 ch 10-bit ADC, RLL0024A (VQFN-24)", Alternate Manufacturer="Texas Instruments", Alternate PartNumber=MSP430FR2100IRLLT
U4: library part CMP-0077328-2, "40-V Ultralow-Iq Low-Dropout Regulator, DBV0005A (SOT-23-5)", Alternate Manufacturer="Texas Instruments"
ZZ1: library part CMP-0077236-1
ZZ5: library part CMP-0003616-3

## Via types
v1: diameter 24, hole 12, Top Layer to Bottom Layer, tented both sides, 36 vias
v2: diameter 19.68, hole 7.87, Top Layer to Bottom Layer, tented both sides, 4 vias

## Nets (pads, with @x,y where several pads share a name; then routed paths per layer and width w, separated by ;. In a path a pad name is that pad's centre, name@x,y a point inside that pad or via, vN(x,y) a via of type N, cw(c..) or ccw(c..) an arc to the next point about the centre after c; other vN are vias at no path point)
GND: C1.1 C2.1 C3.2 C4.2 C5.2 C6.1 C7.2 C8.2 C9.1 C10.2 C11.2 C12.1 C13.2 C16.1 C17.1 D3.1 D4.1 D5.1 J1.1 J2.1 J3.2 J9.1 J9.2 R2.1 R4.1 R9.1 R10.2 R11.2 RP1.1 RP2.1 TP2.1 U1.4 U1.9 U2.4 U2.9 U3.4 U3.25 U4.3 U4.4 | length 133.5
  Top Layer w7: C9.1@382.22,1142.85 432.08,1142.85 435.51,1146.28 437.44,1146.28 447.49,1146.28 U3.4@447.93,1146.72 486.31,1146.72 U3.25@506,1166.4
  other v2: 1605,967.84 1605,1011.15 1590,1712.35 1590,1755.65
ID1: R1.1 R2.2 U3.17 | length 527.9
  Top Layer w7.5: U3.17@564.07,1201.83 568.99,1201.83 579.79,1212.63 579.79,1239.21 v1(579,1240)
  Top Layer w10: R1.1@435.94,1608.75 434.82,1607.64 434.82,1538.21 R2.2@433.71,1537.1 433.76,1537.05 v1(463,1537) v1(463,1537)
  Signal Layer 1 w7.5: v1(463,1537) 486.62,1513.38 543,1513.38 579,1477.38 v1(579,1240)
ID2: R3.1 R4.2 U3.16 | length 514
  Top Layer w7.5: U3.16@564.07,1186.09 590.62,1186.09 596.54,1192 v1(601,1192)
  Top Layer w10: R3.1@515.94,1608.75 514.82,1607.64 514.82,1538.21 R4.2@513.71,1537.1 513.76,1537.05 v1(545,1537) v1(545,1537)
  Signal Layer 1 w8: v1(545,1537) 604,1478 604,1195 v1(601,1192)
ID3: R8.1 R9.2 U3.15 | length 534.9
  Top Layer w7.5: U3.15@564.07,1166.4 566.04,1168.37 625.03,1168.37 v1(627,1170.34) ; R8.1@596.95,1608.75 595.84,1607.64 595.84,1538.21 R9.2@594.73,1537.1 594.78,1537.05 v1(625,1537) v1(625,1537)
  Signal Layer 1 w8: v1(625,1537) 627,1535 v1(627,1170.34)
IN1: J6.2 TP8.1 U1.6 | length 779.3
  Top Layer w8: 1524.83,998.13 1526.05,999.34 U1.6@1567.6,999.34
  Top Layer w12: TP8.1@1158,1142 1158,1080.41 1245.28,993.13 1519.83,993.13 1524.83,998.13
  Top Layer w16: J6.2@921,1064 928.13,1071.13 963.13,1071.13 1034.27,1142.27 TP8.1@1158,1142
IN1_B: J5.2 TP4.1 U2.6 | length 682.3
  Top Layer w8: 1507.68,1743.69 U2.6@1552.6,1743.84
  Top Layer w14: J5.2@931,1739 1014.43,1739 TP4.1@1087.72,1812.28 1204.72,1812.28 1269.13,1747.87 1415.36,1747.87 1423.11,1740.13 1506.68,1740.13 1507.68,1741.13
IN2: J6.4 TP9.1 U1.5 | length 669.4
  Top Layer w8: 1531.02,1019.02 U1.5@1567.6,1019.02
  Top Layer w14: J6.4@921,964 1046.25,964 1063.25,981 TP9.1@1158,981 ; v1(1256,1019) 1531,1019
  Bottom Layer w14: TP9.1@1158,981 1177.04,981 1215.04,1019 v1(1256,1019)
IN2_B: J5.4 TP5.1 U2.5 | length 685.4
  Top Layer w8: 1515,1763 U2.5@1552.6,1763.53
  Top Layer w14: 1432.58,1763 1515,1763
  Top Layer w16: J5.4@931,1639 1030.9,1639 1074.19,1682.28 TP5.1@1087.72,1682.28 ; v1(1333,1778) 1417.58,1778 1432.58,1763
  Bottom Layer w16: TP5.1@1087.72,1682.28 1183.43,1778 v1(1333,1778)
MODE: J2.2 J6.6 TP10.1 U1.7 | length 1610.3
  Top Layer w8: 1501,969 1523.37,969 1534.02,979.65 U1.7@1567.6,979.65
  Top Layer w14: J2.2@109.76,706.48 215.62,812.34 869.34,812.34 J6.6@921,864 1110,864 TP10.1@1158,816 1161,816 1313,968 1501,969
MODE_B: J5.6 TP6.1 U2.7 | length 709.2
  Top Layer w8: 1507,1712 1519,1724 U2.7@1552.6,1724.16
  Top Layer w16: J5.6@931,1539 937.64,1545.64 1081.07,1545.64 TP6.1@1087.72,1552.28 1089,1551 1190,1551 1363,1724 1406.89,1724 1418.89,1712 1507,1712
MODE_MCU: J5.5 J6.5 U3.11 | length 1084.4
  Top Layer w7.5: v1(541,1069) 541.25,1069.25 541.25,1108.14 U3.11@541.43,1108.33
  Signal Layer 1 w12: v1(706,1539) 706,1535.75 714,1527.75 v1(714,1015) 711.7,1012.7 711.7,973.3 J6.5@821,864
  Signal Layer 2 w12: v1(541,1069) 660,1069 v1(714,1015) ; v1(706,1539) J5.5@831,1539
NetC1_2: C1.2 R12.2 U4.1 | length 173.1
  Top Layer w12: C1.2@670.53,94 670.53,144.87 687.26,161.6 U4.1@695.13,161.6 734.98,161.6 767.46,194.08 R12.2@767.46,199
